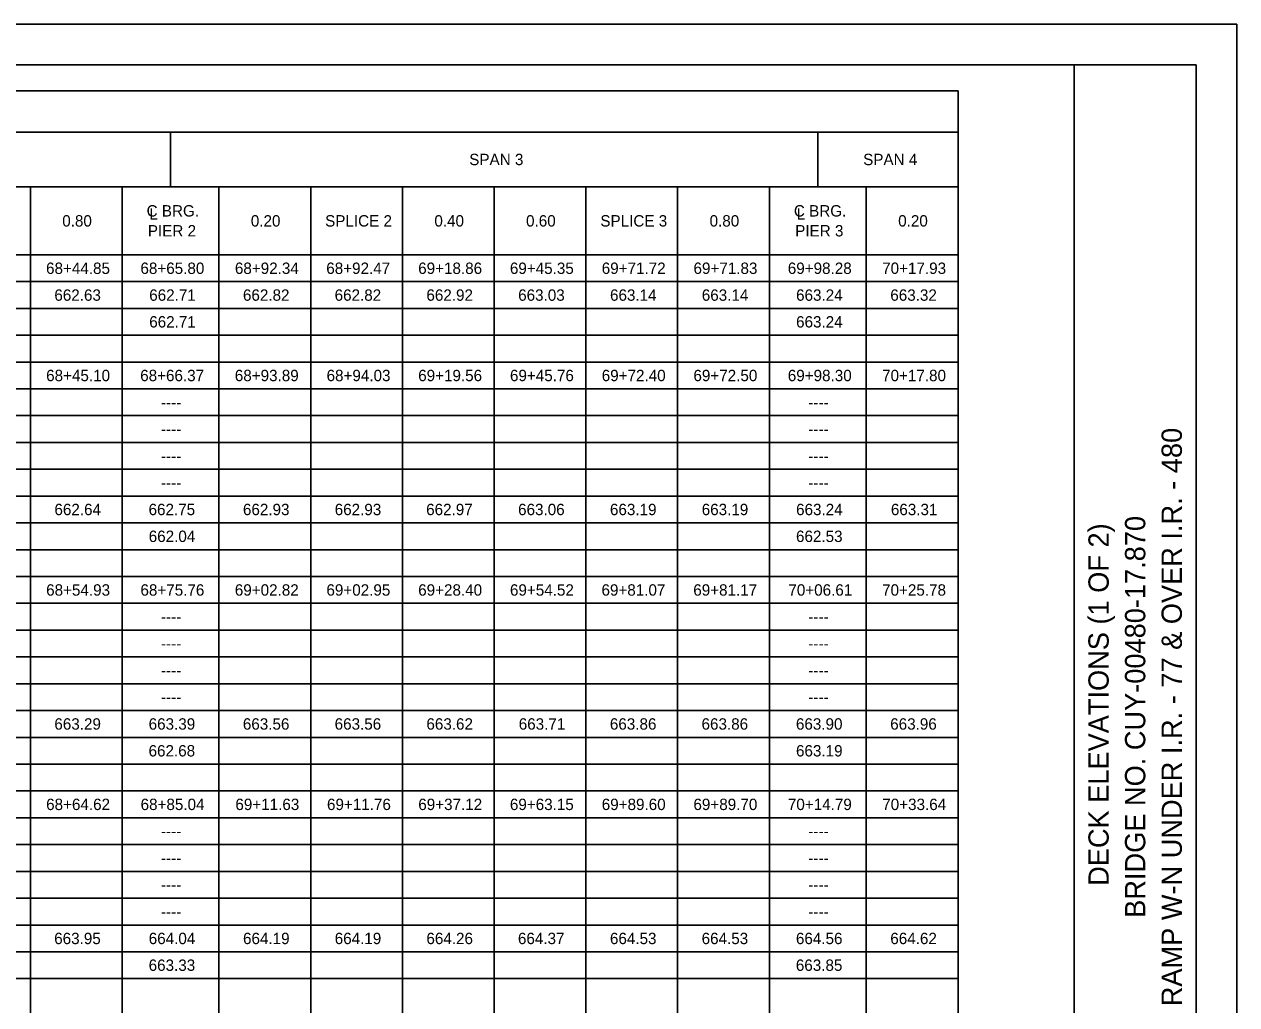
# Model space of a CAD drawing. Extents: x 0 to 34, y 0 to 22.
# Drawn here: x 19.08 to 34, y 9.94 to 22 of the extents above; entities that cross this region are included whole.
import ezdxf

# ---------------------------------------------------------------- set-up
doc = ezdxf.new("R2010")
doc.units = 0
for name, color, linetype in [('SH_Border', 7, 'Continuous'), ('SH_Cut_Line', 7, 'Continuous'), ('SH_Data', 7, 'Continuous'), ('SH_Text', 7, 'Continuous')]:
    doc.layers.add(name, color=color, linetype=linetype)

msp = doc.modelspace()

# ---------------------------------------------------------------- linework, layer by layer
at = {"layer": 'SH_Border'}
msp.add_line((32, 0.5), (32, 21.5), dxfattribs=at)
msp.add_lwpolyline([(1.5, 21.5), (33.5, 21.5), (33.5, 0.5), (1.5, 0.5)], close=True, dxfattribs=at)
at = {"layer": 'SH_Cut_Line'}
msp.add_lwpolyline([(0, 0), (34, 0), (34, 22), (0, 22)], close=True, dxfattribs=at)
at = {"layer": 'SH_Text'}
for p, q in [((2.8, 21.18), (30.572, 21.18)), ((30.572, 21.18), (30.572, 2.349)), ((2.8, 20.673), (30.572, 20.673)), ((20.883, 20.673), (20.883, 20.001)), ((28.847, 20.673), (28.847, 20.001)), ((2.8, 20.001), (30.572, 20.001)), ((19.159, 20.001), (19.159, 2.349)), ((20.287, 20.001), (20.287, 2.349)), ((21.479, 20.001), (21.479, 2.349)), ((22.608, 20.001), (22.608, 2.349)), ((23.736, 20.001), (23.736, 2.349)), ((24.865, 20.001), (24.865, 2.349)), ((25.994, 20.001), (25.994, 2.349)), ((27.122, 20.001), (27.122, 2.349)), ((28.251, 20.001), (28.251, 2.349)), ((29.443, 20.001), (29.443, 2.349)), ((2.8, 19.164), (30.572, 19.164)), ((4.195, 18.834), (30.572, 18.834)), ((4.195, 18.504), (30.572, 18.504)), ((2.8, 18.175), (30.572, 18.175)), ((2.8, 17.845), (30.572, 17.845)), ((4.195, 17.515), (30.572, 17.515)), ((4.195, 17.186), (30.572, 17.186)), ((4.195, 16.856), (30.572, 16.856)), ((4.195, 16.526), (30.572, 16.526)), ((4.195, 16.196), (30.572, 16.196)), ((4.195, 15.867), (30.572, 15.867)), ((2.8, 15.537), (30.572, 15.537)), ((2.8, 15.207), (30.572, 15.207)), ((4.195, 14.878), (30.572, 14.878)), ((4.195, 14.548), (30.572, 14.548)), ((4.195, 14.218), (30.572, 14.218)), ((4.195, 13.889), (30.572, 13.889)), ((4.195, 13.559), (30.572, 13.559)), ((4.195, 13.229), (30.572, 13.229)), ((2.8, 12.899), (30.572, 12.899)), ((2.8, 12.57), (30.572, 12.57)), ((4.195, 12.24), (30.572, 12.24)), ((4.195, 11.91), (30.572, 11.91)), ((4.195, 11.581), (30.572, 11.581)), ((4.195, 11.251), (30.572, 11.251)), ((4.195, 10.921), (30.572, 10.921)), ((4.195, 10.591), (30.572, 10.591)), ((2.8, 10.262), (30.572, 10.262))]:
    msp.add_line(p, q, dxfattribs=at)

# ---------------------------------------------------------------- texts
at = {"layer": 'SH_Data'}
for s, p in [('RAMP W-N UNDER I.R. - 77 & OVER I.R. - 480', (33.325, 9.922)), ('DECK ELEVATIONS (1 OF 2)', (32.425, 11.403)), ('BRIDGE NO. CUY-00480-17.870', (32.875, 11.01))]:
    msp.add_text(s, height=0.25, rotation=90, dxfattribs=at).set_placement(p)
at = {"layer": 'SH_Text'}
for s, p in [('SPAN 3', (24.558, 20.267)), ('SPAN 4', (29.404, 20.267)), ('C BRG.        ', (20.589, 19.635)), ('L', (20.622, 19.596)), ('C BRG.         ', (28.552, 19.635)), ('L', (28.585, 19.596)), ('0.80', (19.551, 19.512)), ('0.20', (21.871, 19.512)), ('SPLICE 2', (22.785, 19.512)), ('0.40', (24.129, 19.512)), ('0.60', (25.257, 19.512)), ('SPLICE 3', (26.171, 19.512)), ('0.80', (27.515, 19.512)), ('0.20', (29.835, 19.512)), ('PIER 2', (20.604, 19.39)), ('PIER 3', (28.568, 19.39)), ('68+44.85', (19.352, 18.929)), ('68+65.80', (20.513, 18.929)), ('68+92.34', (21.675, 18.929)), ('68+92.47', (22.799, 18.929)), ('69+18.86', (23.93, 18.929)), ('69+45.35', (25.058, 18.929)), ('69+71.72', (26.188, 18.929)), ('69+71.83', (27.317, 18.929)), ('69+98.28', (28.477, 18.929)), ('70+17.93', (29.638, 18.929)), ('662.63', (19.454, 18.599)), ('662.71', (20.621, 18.599)), ('662.82', (21.774, 18.599)), ('662.82', (22.902, 18.599)), ('662.92', (24.031, 18.599)), ('663.03', (25.16, 18.599)), ('663.14', (26.29, 18.599)), ('663.14', (27.419, 18.599)), ('663.24', (28.579, 18.599)), ('663.32', (29.738, 18.599)), ('662.71', (20.621, 18.27)), ('663.24', (28.579, 18.27)), ('68+45.10', (19.353, 17.61)), ('68+66.37', (20.51, 17.61)), ('68+93.89', (21.674, 17.61)), ('68+94.03', (22.803, 17.61)), ('69+19.56', (23.93, 17.61)), ('69+45.76', (25.059, 17.61)), ('69+72.40', (26.188, 17.61)), ('69+72.50', (27.316, 17.61)), ('69+98.30', (28.477, 17.61)), ('70+17.80', (29.637, 17.61)), ('----', (20.766, 17.28)), ('----', (28.73, 17.28)), ('----', (20.766, 16.951)), ('----', (28.73, 16.951)), ('----', (20.766, 16.621)), ('----', (28.73, 16.621)), ('----', (20.766, 16.291)), ('----', (28.73, 16.291)), ('662.64', (19.455, 15.962)), ('662.75', (20.613, 15.962)), ('662.93', (21.774, 15.962)), ('662.93', (22.903, 15.962)), ('662.97', (24.028, 15.962)), ('663.06', (25.159, 15.962)), ('663.19', (26.289, 15.962)), ('663.19', (27.418, 15.962)), ('663.24', (28.579, 15.962)), ('663.31', (29.745, 15.962)), ('662.04', (20.615, 15.632)), ('662.53', (28.578, 15.632)), ('68+54.93', (19.353, 14.972)), ('68+75.76', (20.513, 14.972)), ('69+02.82', (21.674, 14.972)), ('69+02.95', (22.801, 14.972)), ('69+28.40', (23.93, 14.972)), ('69+54.52', (25.059, 14.972)), ('69+81.07', (26.185, 14.972)), ('69+81.17', (27.314, 14.972)), ('70+06.61', (28.484, 14.972)), ('70+25.78', (29.637, 14.972)), ('----', (20.766, 14.643)), ('----', (28.73, 14.643)), ('----', (20.766, 14.313)), ('----', (28.73, 14.313)), ('----', (20.766, 13.983)), ('----', (28.73, 13.983)), ('----', (20.766, 13.654)), ('----', (28.73, 13.654)), ('663.29', (19.454, 13.324)), ('663.39', (20.614, 13.324)), ('663.56', (21.773, 13.324)), ('663.56', (22.902, 13.324)), ('663.62', (24.031, 13.324)), ('663.71', (25.167, 13.324)), ('663.86', (26.288, 13.324)), ('663.86', (27.416, 13.324)), ('663.90', (28.577, 13.324)), ('663.96', (29.737, 13.324)), ('662.68', (20.613, 12.994)), ('663.19', (28.578, 12.994)), ('68+64.62', (19.353, 12.335)), ('68+85.04', (20.515, 12.335)), ('69+11.63', (21.681, 12.335)), ('69+11.76', (22.808, 12.335)), ('69+37.12', (23.931, 12.335)), ('69+63.15', (25.058, 12.335)), ('69+89.60', (26.188, 12.335)), ('69+89.70', (27.316, 12.335)), ('70+14.79', (28.478, 12.335)), ('70+33.64', (29.639, 12.335)), ('----', (20.766, 12.005)), ('----', (28.73, 12.005)), ('----', (20.766, 11.675)), ('----', (28.73, 11.675)), ('----', (20.766, 11.346)), ('----', (28.73, 11.346)), ('----', (20.766, 11.016)), ('----', (28.73, 11.016)), ('663.95', (19.452, 10.686)), ('664.04', (20.615, 10.686)), ('664.19', (21.775, 10.686)), ('664.19', (22.903, 10.686)), ('664.26', (24.031, 10.686)), ('664.37', (25.157, 10.686)), ('664.53', (26.289, 10.686)), ('664.53', (27.417, 10.686)), ('664.56', (28.577, 10.686)), ('664.62', (29.738, 10.686)), ('663.33', (20.614, 10.357)), ('663.85', (28.576, 10.357))]:
    msp.add_text(s, height=0.14, dxfattribs=at).set_placement(p)

doc.saveas('drawing.dxf')
